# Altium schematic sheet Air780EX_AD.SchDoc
size 431 x 279 mm
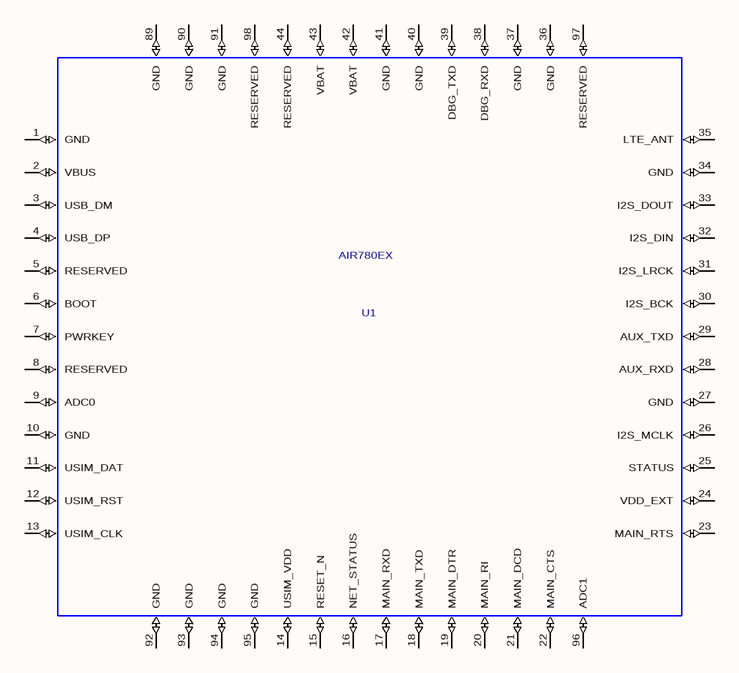
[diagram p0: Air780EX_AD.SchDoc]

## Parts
U1  AIR780EX  [AIR780EX]

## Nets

Not connected (* = marked no-connect by the designer): U1 1(GND) 2(VBUS) 3(USB_DM) 4(USB_DP) 5(RESERVED) 6(BOOT) 7(PWRKEY) 8(RESERVED) 9(ADC0) 10(GND) 11(USIM_DAT) 12(USIM_RST) 13(USIM_CLK) 14(USIM_VDD) 15(RESET_N) 16(NET_STATUS) 17(MAIN_RXD) 18(MAIN_TXD) 19(MAIN_DTR) 20(MAIN_RI) 21(MAIN_DCD) 22(MAIN_CTS) 23(MAIN_RTS) 24(VDD_EXT) 25(STATUS) 26(I2S_MCLK) 27(GND) 28(AUX_RXD) 29(AUX_TXD) 30(I2S_BCK) 31(I2S_LRCK) 32(I2S_DIN) 33(I2S_DOUT) 34(GND) 35(LTE_ANT) 36(GND) 37(GND) 38(DBG_RXD) 39(DBG_TXD) 40(GND) 41(GND) 42(VBAT) 43(VBAT) 44(RESERVED) 89(GND) 90(GND) 91(GND) 92(GND) 93(GND) 94(GND) 95(GND) 96(ADC1) 97(RESERVED) 98(RESERVED)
